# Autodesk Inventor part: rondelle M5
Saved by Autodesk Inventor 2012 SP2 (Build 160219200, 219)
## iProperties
Created: 2013-04
Part Number: rondelle M5
Material: Default
Document SubType Name: Modeling
Designer: papa
Density: 1 g/cm^3
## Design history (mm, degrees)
node "rondelle M51"
node "rondelle M5"
node "Base1"
